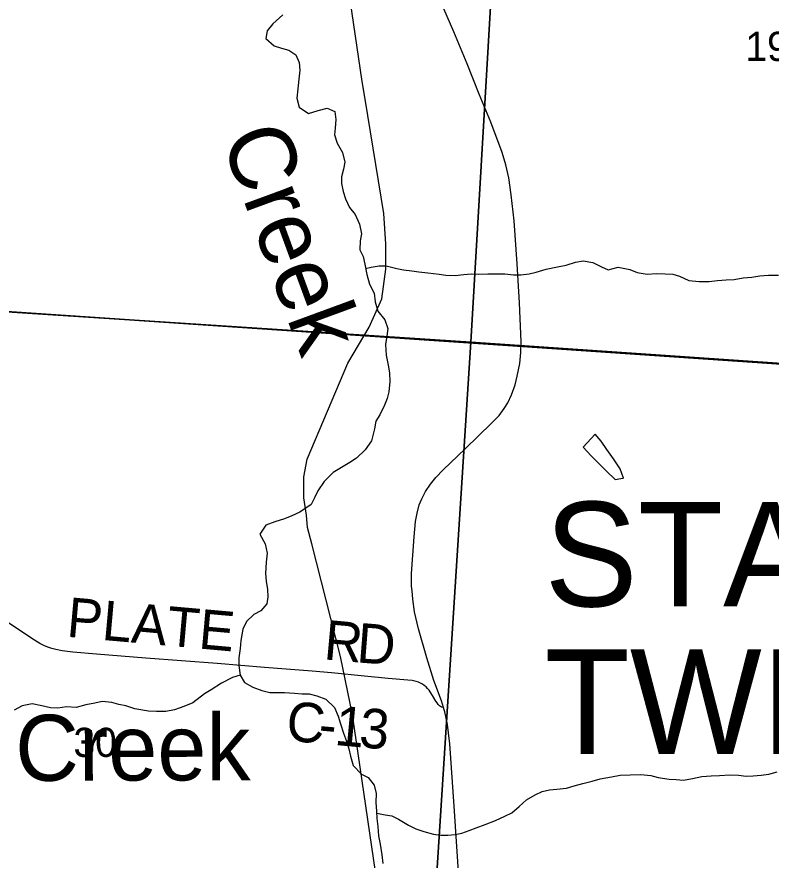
# Model space of a CAD drawing. Extents: x 0 to 34, y 0 to 22.
# Drawn here: x 4.875 to 5.957, y 18.11 to 19.32 of the extents above; entities that cross this region are included whole.
import ezdxf

# ---------------------------------------------------------------- set-up
doc = ezdxf.new("R2010")
doc.units = 0
for name, color, linetype in [('GM_X_Corporation', 7, 'Continuous'), ('GM_X_County_Road', 7, 'Continuous'), ('GM_X_County_Road_Text', 7, 'Continuous'), ('GM_X_Minor_Lake', 7, 'Continuous'), ('GM_X_Minor_River', 7, 'Continuous'), ('GM_X_Minor_River_Text', 7, 'Continuous'), ('GM_X_Rail_Line', 7, 'Continuous'), ('GM_X_Section_Text', 7, 'Continuous'), ('GM_X_State_Route', 7, 'Continuous'), ('GM_X_Township_Text', 7, 'Continuous')]:
    doc.layers.add(name, color=color, linetype=linetype)

msp = doc.modelspace()

# ---------------------------------------------------------------- linework, layer by layer
at = {"layer": 'GM_X_Corporation'}
for points in [[(8.9, 18.631), (8.9, 20.9), (3.6477, 20.9), (3.6464, 20.8827), (3.5665, 19.797), (3.566, 19.7906), (3.507, 18.9883), (4.2931, 18.935), (4.421, 18.9263), (4.4362, 18.9253), (5.6003, 18.8464), (6.4706, 18.7873), (6.895, 18.7585), (7.0255, 18.7497), (7.0714, 18.7466), (7.0845, 18.7457), (7.389, 18.725), (7.8088, 18.6965), (7.8353, 18.6952)], [(4.594, 19.9182), (5.5855, 19.8646), (5.5263, 18.8526), (4.5309, 18.9179)], [(5.5855, 19.8646), (6.5798, 19.8114), (6.5391, 18.7835), (5.5263, 18.8526)], [(4.5309, 18.9179), (5.5263, 18.8526), (5.4592, 17.8072), (4.4596, 17.8697), (4.5247, 18.9179)], [(6.5391, 18.7835), (6.4386, 17.7441), (5.4592, 17.8072), (5.5263, 18.8526)]]:
    msp.add_lwpolyline(points, close=True, dxfattribs=at)
at = {"layer": 'GM_X_County_Road'}
msp.add_lwpolyline([(5.4872, 18.3284), (5.4844, 18.3292), (5.4816, 18.3307), (5.4795, 18.3329), (5.4778, 18.3352), (5.4761, 18.3377), (5.4715, 18.3457), (5.4682, 18.3511), (5.4663, 18.3536), (5.4642, 18.356), (5.462, 18.3583), (5.4595, 18.3603), (5.4569, 18.362), (5.454, 18.3635), (5.4511, 18.3648), (5.4481, 18.3657), (5.4419, 18.3671), (5.4357, 18.3679), (5.4078, 18.3703), (5.3738, 18.3733), (5.3261, 18.3782), (5.2984, 18.3807), (5.2302, 18.3859), (5.1622, 18.3918), (5.0599, 18.3994), (4.989, 18.4049), (4.9552, 18.408), (4.9398, 18.41), (4.9307, 18.4116), (4.9247, 18.4132), (4.9189, 18.4151), (4.9133, 18.4175), (4.9078, 18.4204), (4.8999, 18.4251), (4.8588, 18.4526)], dxfattribs=at)
at = {"layer": 'GM_X_Minor_Lake'}
for p, q in [((5.7049, 18.7208), (5.6877, 18.7021)), ((5.7133, 18.7107), (5.7049, 18.7208)), ((5.7218, 18.6986), (5.7133, 18.7107)), ((5.6877, 18.7021), (5.6991, 18.6897)), ((5.731, 18.6854), (5.7218, 18.6986)), ((5.6991, 18.6897), (5.7114, 18.6773)), ((5.7405, 18.6711), (5.731, 18.6854)), ((5.7114, 18.6773), (5.7209, 18.6675)), ((5.7456, 18.6575), (5.7405, 18.6711)), ((5.7209, 18.6675), (5.7335, 18.6555)), ((5.7335, 18.6555), (5.7418, 18.6569)), ((5.7418, 18.6569), (5.7456, 18.6575))]:
    msp.add_line(p, q, dxfattribs=at)
at = {"layer": 'GM_X_Minor_River'}
for p, q in [((5.3831, 18.9604), (5.3948, 18.9624)), ((5.3948, 18.9624), (5.4047, 18.9625)), ((5.4047, 18.9625), (5.4199, 18.9585)), ((5.6506, 18.961), (5.6631, 18.9634)), ((5.6631, 18.9634), (5.6767, 18.9676)), ((5.6767, 18.9676), (5.6876, 18.9696)), ((5.6876, 18.9696), (5.7016, 18.9671)), ((5.7016, 18.9671), (5.7138, 18.9608)), ((5.3753, 18.9585), (5.3831, 18.9604)), ((5.4199, 18.9585), (5.4297, 18.9567)), ((5.4297, 18.9567), (5.4418, 18.9553)), ((5.4418, 18.9553), (5.4517, 18.9535)), ((5.4517, 18.9535), (5.4645, 18.9524)), ((5.4645, 18.9524), (5.4808, 18.9503)), ((5.4808, 18.9503), (5.4907, 18.9489)), ((5.5039, 18.9483), (5.5164, 18.9499)), ((5.5164, 18.9499), (5.527, 18.9507)), ((5.527, 18.9507), (5.538, 18.9501)), ((5.538, 18.9501), (5.5508, 18.9506)), ((5.5508, 18.9506), (5.575, 18.9508)), ((5.575, 18.9508), (5.5875, 18.9494)), ((5.5875, 18.9494), (5.5981, 18.9495)), ((5.5981, 18.9495), (5.6099, 18.9507)), ((5.6099, 18.9507), (5.62, 18.9531)), ((5.62, 18.9531), (5.6344, 18.9574)), ((5.6344, 18.9574), (5.6506, 18.961)), ((5.7138, 18.9608), (5.7237, 18.9567)), ((5.7237, 18.9567), (5.738, 18.9602)), ((5.738, 18.9602), (5.7547, 18.957)), ((5.7547, 18.957), (5.765, 18.9529)), ((5.765, 18.9529), (5.7794, 18.9504)), ((5.7794, 18.9504), (5.7922, 18.9513)), ((5.7922, 18.9513), (5.8051, 18.951)), ((5.8051, 18.951), (5.8161, 18.9503)), ((5.8161, 18.9503), (5.8259, 18.9474)), ((5.4907, 18.9489), (5.5039, 18.9483)), ((5.8259, 18.9474), (5.8392, 18.9411)), ((5.8392, 18.9411), (5.854, 18.9397)), ((5.854, 18.9397), (5.8684, 18.9398)), ((5.8684, 18.9398), (5.8805, 18.9411)), ((5.8805, 18.9411), (5.8929, 18.9423)), ((5.8929, 18.9423), (5.9043, 18.9428)), ((5.9043, 18.9428), (5.9171, 18.9452)), ((5.9171, 18.9452), (5.9296, 18.9461)), ((5.9296, 18.9461), (5.9413, 18.9481)), ((5.9413, 18.9481), (5.9538, 18.9489)), ((5.9538, 18.9489), (5.9682, 18.9491)), ((5.1843, 18.3716), (5.1685, 18.3635)), ((5.1952, 18.375), (5.1843, 18.3716)), ((5.1685, 18.3635), (5.1538, 18.3539)), ((5.144, 18.3481), (5.1275, 18.3351)), ((5.1538, 18.3539), (5.144, 18.3481)), ((4.8967, 18.3338), (4.8824, 18.331)), ((4.9107, 18.3309), (4.8967, 18.3338)), ((4.9864, 18.3346), (4.9739, 18.3322)), ((4.997, 18.3373), (4.9864, 18.3346)), ((5.011, 18.3359), (4.997, 18.3373)), ((5.0212, 18.3326), (5.011, 18.3359)), ((5.0311, 18.3308), (5.0212, 18.3326)), ((5.1275, 18.3351), (5.1143, 18.3301)), ((4.8824, 18.331), (4.8707, 18.3248)), ((4.9229, 18.3279), (4.9107, 18.3309)), ((4.9335, 18.3277), (4.9229, 18.3279)), ((4.9459, 18.3293), (4.9335, 18.3277)), ((4.9596, 18.3287), (4.9459, 18.3293)), ((4.9739, 18.3322), (4.9596, 18.3287)), ((5.044, 18.3268), (5.0311, 18.3308)), ((5.0637, 18.3232), (5.044, 18.3268)), ((5.075, 18.3229), (5.0637, 18.3232)), ((5.0883, 18.323), (5.075, 18.3229)), ((5.1011, 18.3254), (5.0883, 18.323)), ((5.1143, 18.3301), (5.1011, 18.3254)), ((5.954, 18.2331), (5.9661, 18.2362)), ((5.7006, 18.2228), (5.7119, 18.226)), ((5.7119, 18.226), (5.7281, 18.2288)), ((5.7281, 18.2288), (5.7406, 18.2312)), ((5.7406, 18.2312), (5.7553, 18.2321)), ((5.7553, 18.2321), (5.7705, 18.2322)), ((5.7705, 18.2322), (5.7849, 18.2308)), ((5.7849, 18.2308), (5.7955, 18.2283)), ((5.7955, 18.2283), (5.811, 18.2257)), ((5.811, 18.2257), (5.8212, 18.2251)), ((5.8212, 18.2251), (5.8318, 18.2244)), ((5.8318, 18.2244), (5.8447, 18.2268)), ((5.8447, 18.2268), (5.8579, 18.2296)), ((5.8579, 18.2296), (5.8715, 18.2305)), ((5.8715, 18.2305), (5.8832, 18.2309)), ((5.8832, 18.2309), (5.898, 18.2318)), ((5.898, 18.2318), (5.9105, 18.2312)), ((5.9105, 18.2312), (5.9218, 18.2302)), ((5.9218, 18.2302), (5.9317, 18.2306)), ((5.9317, 18.2306), (5.943, 18.2315)), ((5.943, 18.2315), (5.954, 18.2331)), ((5.6394, 18.2102), (5.6496, 18.2114)), ((5.6496, 18.2114), (5.6636, 18.213)), ((5.6636, 18.213), (5.6745, 18.2162)), ((5.6745, 18.2162), (5.687, 18.2193)), ((5.687, 18.2193), (5.7006, 18.2228)), ((5.6062, 18.1962), (5.6186, 18.2032)), ((5.6186, 18.2032), (5.6288, 18.2078)), ((5.6288, 18.2078), (5.6394, 18.2102)), ((5.5957, 18.1866), (5.6062, 18.1962)), ((5.3912, 18.177), (5.4036, 18.1747)), ((5.575, 18.1724), (5.5852, 18.1775)), ((5.5852, 18.1775), (5.5957, 18.1866)), ((5.4036, 18.1747), (5.4131, 18.1732)), ((5.4131, 18.1732), (5.4226, 18.1684)), ((5.4226, 18.1684), (5.437, 18.1598)), ((5.5471, 18.1608), (5.5618, 18.1666)), ((5.5618, 18.1666), (5.575, 18.1724)), ((5.437, 18.1598), (5.4473, 18.1546)), ((5.4473, 18.1546), (5.4587, 18.1505)), ((5.5135, 18.1484), (5.5241, 18.1519)), ((5.5241, 18.1519), (5.5339, 18.1558)), ((5.5339, 18.1558), (5.5471, 18.1608)), ((5.4587, 18.1505), (5.4727, 18.1469)), ((5.4727, 18.1469), (5.4833, 18.1455)), ((5.4833, 18.1455), (5.4931, 18.1452)), ((5.4931, 18.1452), (5.5037, 18.1464)), ((5.5037, 18.1464), (5.5135, 18.1484))]:
    msp.add_line(p, q, dxfattribs=at)
for points in [[(5.2566, 19.3227), (5.242, 19.3097), (5.2338, 19.2994), (5.232, 19.2887), (5.2442, 19.2782), (5.2544, 19.2745), (5.265, 19.2716), (5.2749, 19.2653), (5.2799, 19.2543), (5.2808, 19.2429), (5.2794, 19.2301), (5.278, 19.2164), (5.2766, 19.2031), (5.2801, 19.1899), (5.2934, 19.1809), (5.3074, 19.1852), (5.3199, 19.1884), (5.3312, 19.1839), (5.3325, 19.1722), (5.3318, 19.16), (5.3308, 19.1502), (5.3343, 19.1381), (5.342, 19.1249), (5.3455, 19.1109), (5.3437, 19.101), (5.3408, 19.09), (5.3405, 19.0805), (5.3432, 19.0688), (5.3463, 19.0582), (5.3521, 19.0462), (5.3602, 19.036), (5.3667, 19.022), (5.3695, 19.0084), (5.3673, 18.9982), (5.367, 18.9853), (5.3716, 18.9755), (5.374, 18.9645), (5.3772, 18.9498), (5.3811, 18.9362), (5.3876, 18.923), (5.3889, 18.9105), (5.3928, 18.8972), (5.4027, 18.8848), (5.407, 18.8723), (5.4059, 18.8613), (5.4038, 18.8496), (5.4047, 18.8341), (5.4078, 18.8197), (5.4098, 18.8087), (5.4099, 18.7962), (5.4085, 18.7814), (5.4063, 18.7719), (5.4026, 18.7624), (5.3956, 18.7487), (5.39, 18.7392), (5.3882, 18.7282), (5.3838, 18.7111), (5.3748, 18.6985), (5.3624, 18.6863), (5.3527, 18.6801), (5.3429, 18.6743), (5.3286, 18.6659), (5.3158, 18.6529), (5.3065, 18.6395), (5.302, 18.6296), (5.2972, 18.6197), (5.281, 18.6086), (5.2693, 18.6036), (5.2588, 18.5993), (5.2452, 18.595), (5.232, 18.59), (5.2234, 18.5774), (5.2311, 18.5634), (5.2339, 18.5498), (5.2325, 18.5369), (5.2318, 18.521), (5.2327, 18.51), (5.2343, 18.4979)], [(5.2343, 18.4979), (5.2348, 18.4873), (5.2333, 18.4774), (5.2247, 18.4671), (5.2149, 18.4621), (5.2041, 18.4521), (5.1989, 18.4411), (5.196, 18.4248), (5.1953, 18.4134), (5.1935, 18.3998), (5.1933, 18.3888), (5.1953, 18.3748), (5.2014, 18.3646), (5.2136, 18.3575), (5.2261, 18.3531), (5.2379, 18.3501), (5.2477, 18.3502), (5.2587, 18.3499), (5.2731, 18.3489), (5.2844, 18.3483), (5.2943, 18.348), (5.3052, 18.3454), (5.3182, 18.3403), (5.3307, 18.3286), (5.3358, 18.3162), (5.3393, 18.3052), (5.3436, 18.2916), (5.3478, 18.2803), (5.3513, 18.2693), (5.3537, 18.2587), (5.3572, 18.2451), (5.3694, 18.2327), (5.3789, 18.2283), (5.3877, 18.2173), (5.3905, 18.2049), (5.3902, 18.192), (5.3911, 18.1799), (5.3915, 18.1693), (5.3928, 18.1579), (5.3936, 18.1446), (5.396, 18.1325), (5.3984, 18.117), (5.4, 18.1045)]]:
    msp.add_lwpolyline(points, dxfattribs=at)
at = {"layer": 'GM_X_Rail_Line'}
msp.add_lwpolyline([(5.4004, 18.0178), (5.3565, 18.3179), (5.3392, 18.4015), (5.2983, 18.5634), (5.2919, 18.587), (5.2905, 18.6045), (5.2864, 18.6295), (5.2867, 18.6593), (5.2915, 18.6851), (5.3496, 18.8224), (5.3806, 18.8744), (5.3985, 18.9151), (5.4041, 18.9575), (5.4041, 18.9937), (5.4016, 19.0373), (5.3783, 19.1779), (5.37, 19.2302), (5.351, 19.3574), (5.3362, 19.4456), (5.311, 19.5437), (5.2889, 19.5998), (5.0925, 20.0787), (5.0288, 20.2329)], dxfattribs=at)
at = {"layer": 'GM_X_State_Route'}
for points in [[(5.4872, 18.3284), (5.4843, 18.3381), (5.4734, 18.3672), (5.463, 18.3997), (5.4513, 18.4415), (5.4457, 18.4656), (5.4429, 18.4839), (5.4419, 18.4961), (5.4414, 18.5024), (5.4414, 18.5133), (5.4413, 18.521), (5.445, 18.5736), (5.4469, 18.5952), (5.4491, 18.6074), (5.4524, 18.6192), (5.4558, 18.6278), (5.4614, 18.6387), (5.4683, 18.6489), (5.4761, 18.6585), (5.4867, 18.6698), (5.5182, 18.6996), (5.5562, 18.7363), (5.5668, 18.7477), (5.5744, 18.7577), (5.5793, 18.7657), (5.5847, 18.777), (5.5899, 18.7917), (5.5931, 18.8038), (5.5966, 18.8222), (5.5983, 18.8377), (5.5987, 18.8533), (5.5964, 18.9092), (5.5931, 18.965), (5.5884, 19.027), (5.5843, 19.0641), (5.5807, 19.0887), (5.5767, 19.107), (5.5713, 19.1249), (5.555, 19.1686), (5.5385, 19.2088), (5.521, 19.252), (5.5021, 19.2979), (5.4152, 19.4973)], [(5.5112, 18.0505), (5.5095, 18.0784), (5.5026, 18.1868), (5.496, 18.2766), (5.4945, 18.2921), (5.4928, 18.3043), (5.4911, 18.3134), (5.4889, 18.3224), (5.4881, 18.3254), (5.4872, 18.3284)]]:
    msp.add_lwpolyline(points, dxfattribs=at)
at = {"layer": 'GM_X_Township_Text'}
msp.add_lwpolyline([(8.9, 18.631), (7.8353, 18.6952), (7.8088, 18.6965), (7.389, 18.725), (7.0845, 18.7457), (7.0714, 18.7466), (7.0255, 18.7497), (6.895, 18.7585), (6.4706, 18.7873), (5.6003, 18.8464), (4.4362, 18.9253), (4.421, 18.9263), (4.2931, 18.935), (3.507, 18.9883), (3.3951, 17.2616), (3.3516, 16.5898), (3.3059, 15.8844), (3.2844, 15.554), (3.2339, 14.7735), (3.1919, 14.1255), (3.1902, 14.1)], dxfattribs=at)

# ---------------------------------------------------------------- texts
at = {"layer": 'GM_X_County_Road_Text'}
for s, height, rotation, p in [('PLATE', 0.05682, 354.906, (4.945, 18.4302)), ('R', 0.0568, 354.861, (5.3141, 18.3977)), ('D', 0.0568, 355.5266, (5.3613, 18.3934)), ('C', 0.0568, 354.7469, (5.2598, 18.2813)), ('1', 0.0568, 354.8082, (5.3295, 18.2749)), ('3', 0.0568, 355.1583, (5.3648, 18.2717)), ('-', 0.0568, 354.7518, (5.3062, 18.277))]:
    msp.add_text(s, height=height, rotation=rotation, dxfattribs=at).set_placement(p)
at = {"layer": 'GM_X_Minor_River_Text'}
for height, rotation, p in [(0.0947, 290.1693, (5.1671, 19.1456)), (0.09469, 0.1706, (4.8724, 18.2232))]:
    msp.add_text('Creek', height=height, rotation=rotation, dxfattribs=at).set_placement(p)
at = {"layer": 'GM_X_Section_Text'}
for s, p in [('19', (5.9205, 19.2563)), ('30', (4.9559, 18.2576))]:
    msp.add_text(s, height=0.04186, rotation=0, dxfattribs=at).set_placement(p)
at = {"layer": 'GM_X_Township_Text'}
for s, p in [('STARR', (5.6321, 18.4736)), ('TWP.', (5.6321, 18.262))]:
    msp.add_text(s, height=0.15, rotation=0, dxfattribs=at).set_placement(p)

doc.saveas('drawing.dxf')
